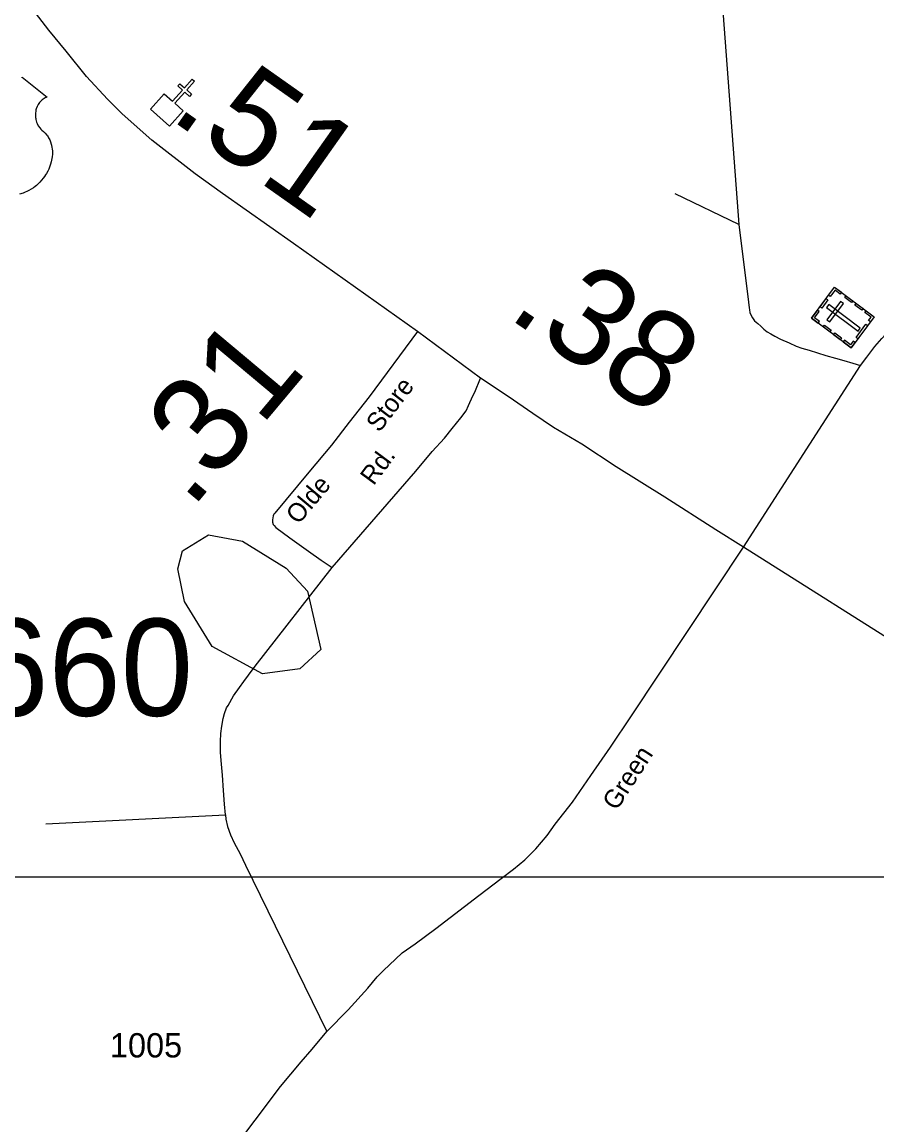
# Model space of a CAD drawing. Extents: x 2093524 to 2270757, y 289120 to 570408.
# Drawn here: x 2123530 to 2127930, y 548423 to 554097 of the extents above; entities that cross this region are included whole.
import ezdxf

# ---------------------------------------------------------------- set-up
doc = ezdxf.new("R2010")
doc.units = 0
for name, color, linetype in [('Exist Cultural Cemetery CELL', 7, 'Continuous'), ('Exist Cultural Church CELL', 7, 'Continuous'), ('Exist Hydrographic Pond Under 1500 Sq Ft', 7, 'Continuous'), ('Exist Road Non-System Type 51', 7, 'Continuous'), ('Exist Road Primary US Attributed', 7, 'Continuous'), ('Exist Road Primary US Mileage Hundredths English Label', 7, 'Continuous'), ('Exist Road Primary US Shield CELL', 7, 'Continuous'), ('Exist Road Secondary Mileage Hundredths English Label', 7, 'Continuous'), ('Exist Road Secondary Type 51 Attributed', 7, 'Continuous'), ('Exist Road Secondary Type 51 Label', 7, 'Continuous'), ('Exist Road Secondary Type 51 Number Label', 7, 'Continuous'), ('Map Preparation Inset Cut Line', 7, 'Continuous')]:
    doc.layers.add(name, color=color, linetype=linetype)

msp = doc.modelspace()

# ---------------------------------------------------------------- linework, layer by layer
at = {"layer": 'Exist Cultural Cemetery CELL'}
for points in [[(2127592.7, 552573.2), (2127711.6, 552732.9), (2127915.8, 552580.8), (2127796.9, 552421.1)], [(2127746.4, 552707), (2127739.6, 552697.9), (2127713.8, 552717.1), (2127689.6, 552684.6), (2127680.6, 552691.3), (2127711.6, 552732.9)], [(2127636.9, 552632.6), (2127667.9, 552674.1), (2127677, 552667.3), (2127646, 552625.8)], [(2127681.3, 552643.1), (2127670.1, 552628.1), (2127832.8, 552507), (2127843.9, 552522)], [(2127671.6, 552565.3), (2127686.6, 552554.1), (2127756.9, 552648.6), (2127741.9, 552659.7)], [(2127798.2, 552654.2), (2127763.4, 552680.1), (2127770.2, 552689.2), (2127805, 552663.4)], [(2127851, 552614.8), (2127816.3, 552640.7), (2127823.1, 552649.8), (2127857.8, 552624)], [(2127627.4, 552547.3), (2127634.2, 552556.4), (2127608.4, 552575.6), (2127632.6, 552608.2), (2127623.7, 552614.8), (2127592.7, 552573.2)], [(2127896, 552554.2), (2127886.8, 552561.1), (2127899.9, 552578.7), (2127867.5, 552602.9), (2127874.2, 552611.8), (2127915.8, 552580.8)], [(2127686.9, 552503), (2127652.1, 552528.9), (2127658.9, 552538), (2127693.7, 552512.1)], [(2127822, 552474), (2127872.7, 552542.1), (2127881.8, 552535.3), (2127831.1, 552467.2)], [(2127740.8, 552462.9), (2127706, 552488.7), (2127712.8, 552497.9), (2127747.6, 552472)], [(2127816.6, 552447.7), (2127807.4, 552454.5), (2127794.2, 552436.9), (2127761.8, 552461), (2127755.2, 552452.1), (2127796.8, 552421.1)]]:
    msp.add_lwpolyline(points, close=True, dxfattribs=at)
at = {"layer": 'Exist Cultural Church CELL'}
msp.add_lwpolyline([(2124261.9, 553728), (2124304.4, 553690.1), (2124355.1, 553746.9), (2124331.3, 553768.2), (2124341.9, 553780.1), (2124365.8, 553758.8), (2124405.9, 553803.7), (2124417.8, 553793), (2124377.7, 553748.2), (2124401.6, 553726.8), (2124391, 553714.9), (2124367.1, 553736.2), (2124316.4, 553679.5), (2124359.3, 553641), (2124288.3, 553561.6), (2124191, 553648.6)], close=True, dxfattribs=at)
at = {"layer": 'Exist Hydrographic Pond Under 1500 Sq Ft'}
msp.add_lwpolyline([(2124766.9, 550744.5), (2124507.7, 550884.2), (2124365.8, 551116.7), (2124331.8, 551284.7), (2124355.8, 551376), (2124488.9, 551458.7), (2124663.8, 551425.6), (2124889.7, 551286.5), (2124998.8, 551169.5), (2125066.9, 550869.7), (2124958.8, 550770.2), (2124766.9, 550744.5)], dxfattribs=at)
at = {"layer": 'Exist Road Non-System Type 51'}
for p, q in [((2127218, 553056.1), (2126891.2, 553212.7)), ((2123652.1, 549972.4), (2124577, 550017.8))]:
    msp.add_line(p, q, dxfattribs=at)
for points in [[(2127635, 554887.5), (2127147.1, 554991.3), (2127127.1, 554991.7), (2127107.1, 554990.1), (2127101.1, 554988.2), (2127095, 554984.3), (2127088.9, 554980.5), (2127084.8, 554976.6), (2127080.7, 554968.6), (2127078.4, 554956.7), (2127077.9, 554932.7), (2127077.8, 554924.7), (2127081, 554886.6), (2127218, 553056.1)], [(2127218, 553056.1), (2127267.9, 552655.1), (2127271.3, 552627.1), (2127273.1, 552617), (2127274.8, 552603), (2127280.6, 552590.9), (2127288.3, 552574.7), (2127300, 552560.5), (2127315.7, 552546.2), (2127331.4, 552531.9), (2127347.1, 552517.5), (2127364.8, 552503.2), (2127382.6, 552492.8), (2127404.3, 552480.4), (2127434, 552465.8), (2127477.7, 552446.9), (2127513.3, 552430.2), (2127543.1, 552419.6), (2127580.9, 552408.8), (2127666.3, 552381.1), (2127716, 552368.1), (2127759.8, 552355.2), (2127805.5, 552342.3), (2127845.3, 552329.5)], [(2125126.6, 551290.5), (2125556.5, 551785.8), (2125640.5, 551888.1), (2125703.9, 551956.8), (2125742.9, 552006), (2125765.5, 552033.5), (2125788, 552061.1), (2125814.7, 552096.5), (2125827.3, 552124.3), (2125850.3, 552173.8), (2125860.7, 552193.6), (2125890.1, 552265)], [(2124577, 550017.8), (2124572.1, 550073.9), (2124567.5, 550143.9), (2124561.1, 550222.1), (2124554.6, 550298.2), (2124551.4, 550340.2), (2124550.6, 550396.3), (2124553.3, 550436.2), (2124558.1, 550474.1), (2124565, 550513.9), (2124571.4, 550539.8), (2124582.1, 550569.6), (2124590.3, 550581.4), (2124617.3, 550630.9), (2124648.2, 550674.2), (2124670.8, 550703.8), (2124695.4, 550737.3), (2124730.4, 550782.6), (2125126.6, 551290.5)], [(2124577, 550017.8), (2124578.5, 549995.7), (2124587.7, 549957.6), (2124602.9, 549915.3), (2124622, 549874.9), (2124652.9, 549818.3), (2124679.7, 549759.7), (2125098.4, 548903.4)]]:
    msp.add_lwpolyline(points, dxfattribs=at)
at = {"layer": 'Exist Road Primary US Attributed'}
for points in [[(2125565.1, 552505.5), (2124926.3, 552958.4), (2124561.6, 553215.7), (2124421.6, 553316.5), (2124197.1, 553489), (2124045.9, 553624.1), (2123969.4, 553699.6), (2123861.8, 553817.8), (2123756.5, 553947.9), (2123668.6, 554055.6), (2123536.5, 554227.9)], [(2127242.4, 551395.8), (2127100.3, 551484.7), (2126837.7, 551651.9), (2126586.9, 551809), (2126411.2, 551924.5), (2126265, 552011.5), (2126158.4, 552083.6), (2126032.2, 552170.1), (2125890.1, 552265), (2125565.1, 552505.5)], [(2129233.2, 550153.8), (2129085, 550246.7), (2128840.1, 550397.7), (2128571.6, 550567.1), (2128160.6, 550815.3), (2127242.4, 551395.8)]]:
    msp.add_lwpolyline(points, dxfattribs=at)
at = {"layer": 'Exist Road Primary US Shield CELL'}
msp.add_lwpolyline([(2123529.9, 553809.9), (2123530, 553813.7), (2123658.6, 553711.3), (2123655.6, 553710.1), (2123648.6, 553706.7), (2123643, 553703.4), (2123634.2, 553697.2), (2123630.4, 553693.8), (2123626.6, 553690.2), (2123623.1, 553686.4), (2123620, 553682.8), (2123616.3, 553677.7), (2123613, 553672.5), (2123609.7, 553666.8), (2123607.3, 553661.9), (2123603.3, 553651.5), (2123601.4, 553645), (2123600.2, 553639.4), (2123598.7, 553628), (2123598.3, 553622.5), (2123598.3, 553617.1), (2123598.6, 553611.4), (2123599.2, 553605.9), (2123600.2, 553600.2), (2123601.1, 553595.2), (2123602.7, 553589.1), (2123604.9, 553581.9), (2123607.7, 553575), (2123613.6, 553563.8), (2123621.2, 553552.4), (2123626.6, 553546.1), (2123631.9, 553540.6), (2123639.8, 553533.9), (2123644.1, 553530.1), (2123649.1, 553525.2), (2123657.1, 553515.8), (2123660.4, 553511.4), (2123663.7, 553506.5), (2123666.7, 553501.4), (2123669.8, 553495.9), (2123672.2, 553491.1), (2123676.7, 553480.1), (2123680, 553469.4), (2123681.5, 553463.8), (2123683.9, 553451.2), (2123684.8, 553444.9), (2123685.8, 553432.6), (2123685.9, 553417.7), (2123684.7, 553403.6), (2123682.1, 553387.1), (2123679.9, 553377.2), (2123676.5, 553365.7), (2123673.2, 553355.8), (2123667.3, 553341.1), (2123662.1, 553330.5), (2123655.4, 553318), (2123650.7, 553310.5), (2123645.3, 553302.4), (2123638.6, 553293.2), (2123630.7, 553283.3), (2123621.2, 553272.9), (2123613.5, 553265.2), (2123603.5, 553256.2), (2123597.4, 553251.2), (2123588.8, 553244.7), (2123576.9, 553236.8), (2123565.2, 553230), (2123555.3, 553224.9), (2123546.5, 553221.1), (2123535.1, 553216.8), (2123516.1, 553211.6)], dxfattribs=at)
at = {"layer": 'Exist Road Secondary Type 51 Attributed'}
for points in [[(2127242.4, 551395.8), (2127845.3, 552329.5), (2127878.1, 552372.8), (2127919.2, 552428), (2127954.1, 552469.3), (2127994.9, 552512.5), (2128066.2, 552573), (2128118.9, 552612), (2128167.5, 552641), (2128226.2, 552673.8), (2128258.5, 552689.1), (2128286.7, 552698.6), (2128340.8, 552705.5), (2128483.1, 552722.6), (2128958.4, 552787), (2129193.2, 552826.2), (2129429.8, 552859.5), (2129706.8, 552907.9), (2129863.2, 552932.7), (2130032, 552971.3), (2130190.9, 553016.1), (2130331.9, 553065.2), (2130826.6, 553244.8)], [(2125565.1, 552505.5), (2125316.2, 552168.6), (2125213.6, 552038.7), (2125123.3, 551920.5), (2125006.4, 551780.9), (2124830.2, 551570.5), (2124826.2, 551564.6), (2124822, 551556.6), (2124819.7, 551546.7), (2124819.5, 551536.7), (2124819.3, 551524.7), (2124823.1, 551512.6), (2124827, 551506.5), (2124836.8, 551496.3), (2124907.6, 551442.9), (2125004.3, 551375), (2125069.3, 551327.7), (2125126.6, 551290.5)], [(2124628.5, 548312.9), (2124729.1, 548446.9), (2124860.6, 548620.2), (2124967.2, 548748), (2125022.6, 548812.9), (2125098.4, 548903.4), (2125208.5, 549015.1), (2125308.8, 549127.1), (2125357.9, 549184.1), (2125390.6, 549217.4), (2125421.3, 549246.8), (2125451.8, 549276.2), (2125486.4, 549307.5), (2125553.3, 549354.1), (2125659, 549434), (2125880.4, 549603.5), (2125996.1, 549691.2), (2126059.1, 549737.9), (2126118, 549786.7), (2126173.2, 549843.6), (2126232.6, 549912.4), (2126273.7, 549969.5), (2126362, 550083.7), (2126456.8, 550219.8), (2126557.7, 550365.7), (2126667, 550527.5), (2127242.4, 551395.8)]]:
    msp.add_lwpolyline(points, dxfattribs=at)
at = {"layer": 'Map Preparation Inset Cut Line'}
msp.add_lwpolyline([(2141792.3, 534352.7), (2122830.6, 534352.7), (2122830.6, 549698.5), (2141792.3, 549698.5)], close=True, dxfattribs=at)

# ---------------------------------------------------------------- texts
at = {"layer": 'Exist Road Primary US Mileage Hundredths English Label'}
for s, rotation, p in [('.51', 324.7964, (2124279.8, 553605.7)), ('.38', 325.5718, (2126018.8, 552583.9))]:
    msp.add_text(s, height=500, rotation=rotation, dxfattribs=at).set_placement(p)
at = {"layer": 'Exist Road Secondary Mileage Hundredths English Label'}
msp.add_text('.31', height=500, rotation=50.0581, dxfattribs=at).set_placement((2124400.3, 551584.7))
at = {"layer": 'Exist Road Secondary Type 51 Label'}
for s, rotation, p in [('Store', 52.6208, (2125368.3, 551981.3)), ('Rd.', 53.5542, (2125339.2, 551708.4)), ('Olde', 50.0549, (2124952.2, 551507.8)), ('Green', 57.1493, (2126590, 550035.4))]:
    msp.add_text(s, height=95, rotation=rotation, dxfattribs=at).set_placement(p)
at = {"layer": 'Exist Road Secondary Type 51 Number Label'}
for s, height, p in [('1660', 500, (2122922.4, 550527.5)), ('1005', 125, (2123982.1, 548769.9))]:
    msp.add_text(s, height=height, dxfattribs=at).set_placement(p)

doc.saveas('drawing.dxf')
